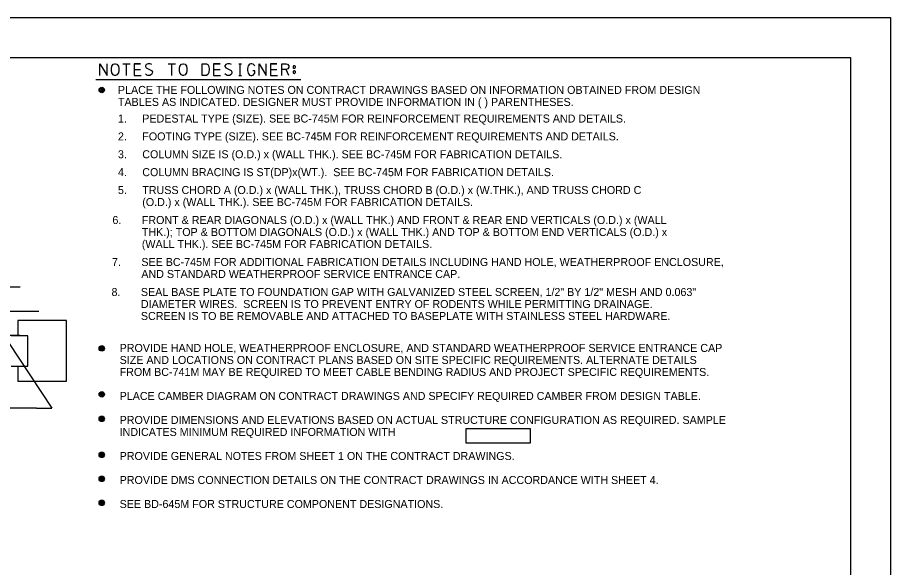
# Model space of a CAD drawing. Extents: x 3831399 to 3833095, y 499014 to 500202.
# Drawn here: x 3832754.1 to 3833081.2, y 499995.8 to 500202 of the extents above; entities that cross this region are included whole.
import ezdxf

# ---------------------------------------------------------------- set-up
doc = ezdxf.new("R2010")
doc.units = 0
for name, color, linetype in [('0-conc', 7, 'Continuous'), ('0-DEVICE ATTACH', 7, 'Continuous'), ('2', 7, 'Continuous'), ('CenterLine', 7, 'Continuous'), ('DIM TXT', 7, 'Continuous'), ('PLT-BNDY', 7, 'Continuous')]:
    doc.layers.add(name, color=color, linetype=linetype)

msp = doc.modelspace()

# ---------------------------------------------------------------- linework, layer by layer
at = {"layer": '0-conc'}
for p, q in [((3832772.44, 500088.38), (3832754.26, 500088.38)), ((3832754.26, 500088.38), (3832754.26, 500082.68)), ((3832772.44, 500065.64), (3832772.44, 500088.38)), ((3832754.26, 500071.31), (3832754.26, 500065.64)), ((3832754.26, 500065.64), (3832772.44, 500065.64))]:
    msp.add_line(p, q, dxfattribs=at)
at = {"layer": '0-DEVICE ATTACH'}
for p, q in [((3832757.96, 500082.68), (3832751.71, 500082.68)), ((3832757.96, 500078.03), (3832757.96, 500082.68)), ((3832757.96, 500071.31), (3832757.96, 500078.03)), ((3832751.71, 500071.31), (3832757.96, 500071.31))]:
    msp.add_line(p, q, dxfattribs=at)
at = {"layer": '2'}
for p, q in [((3832280.16, 500187.03), (3833066.16, 500187.03)), ((3833066.16, 500187.03), (3833066.16, 499623.03))]:
    msp.add_line(p, q, dxfattribs=at)
at = {"layer": 'CenterLine'}
for p, q in [((3832324.19, 500101.07), (3832755.03, 500101.07)), ((3832324.19, 500091.98), (3832755.03, 500091.98)), ((3832706.69, 500091.98), (3832762.11, 500091.98)), ((3832324.19, 500082.88), (3832755.03, 500082.88))]:
    msp.add_line(p, q, dxfattribs=at)
at = {"layer": 'DIM TXT'}
for p, q in [((3832793.5, 500184.7), (3832796.31, 500184.7)), ((3832794.91, 500180.31), (3832794.91, 500184.7)), ((3832794.91, 500180.31), (3832794.91, 500184.7)), ((3832797.75, 500184.7), (3832800.2, 500184.7)), ((3832810.52, 500184.7), (3832813.33, 500184.7)), ((3832811.93, 500180.31), (3832811.93, 500184.7)), ((3832811.93, 500180.31), (3832811.93, 500184.7)), ((3832827.54, 500184.7), (3832829.99, 500184.7)), ((3832836.99, 500184.7), (3832838, 500184.7)), ((3832837.49, 500180.31), (3832837.49, 500184.7)), ((3832848.82, 500184.7), (3832851.27, 500184.7)), ((3832797.75, 500182.52), (3832800.2, 500182.52)), ((3832797.75, 500182.52), (3832800.2, 500182.52)), ((3832827.54, 500182.52), (3832829.99, 500182.52)), ((3832827.54, 500182.52), (3832829.99, 500182.52)), ((3832848.82, 500182.52), (3832851.27, 500182.52)), ((3832848.82, 500182.52), (3832851.27, 500182.52)), ((3832855.72, 500180.31), (3832854.75, 500182.56)), ((3832783.48, 500178.83), (3832860.19, 500178.83)), ((3832836.99, 500180.31), (3832838, 500180.31)), ((3832743.36, 500091.18), (3832767, 500055.57)), ((3832761.18, 500055.57), (3832745.2, 500055.57)), ((3832761.18, 500055.57), (3832767, 500055.57)), ((3832946.33, 500047.84), (3832922.08, 500047.84)), ((3832922.08, 500047.84), (3832922.08, 500042.59)), ((3832946.33, 500042.59), (3832946.33, 500047.84)), ((3832922.08, 500042.59), (3832946.33, 500042.59))]:
    msp.add_line(p, q, dxfattribs=at)
for points in [[(3832784.99, 500180.31), (3832784.99, 500184.7), (3832787.63, 500180.31), (3832787.63, 500184.7)], [(3832790.45, 500184.7), (3832790.78, 500184.7), (3832791.35, 500184.46), (3832791.89, 500183.73), (3832792.02, 500182.87), (3832792.02, 500182.08), (3832791.89, 500181.21), (3832791.32, 500180.49), (3832790.78, 500180.31), (3832790.45, 500180.31), (3832789.95, 500180.49), (3832789.38, 500181.21), (3832789.24, 500182.08), (3832789.24, 500182.87), (3832789.38, 500183.77), (3832789.95, 500184.49), (3832790.45, 500184.7)], [(3832800.2, 500184.7), (3832797.75, 500184.7), (3832797.75, 500180.31), (3832800.37, 500180.31)], [(3832804.46, 500184.39), (3832803.79, 500184.7), (3832803.01, 500184.7), (3832802.31, 500184.39), (3832802.01, 500183.84), (3832802.01, 500183.63), (3832802.34, 500183.11), (3832804.29, 500182.08), (3832804.62, 500181.59), (3832804.59, 500181.18), (3832804.29, 500180.63), (3832803.72, 500180.31), (3832802.91, 500180.31), (3832802.55, 500180.45), (3832802.01, 500180.83)], [(3832815.98, 500184.7), (3832816.32, 500184.7), (3832816.89, 500184.46), (3832817.42, 500183.73), (3832817.56, 500182.87), (3832817.56, 500182.08), (3832817.42, 500181.21), (3832816.85, 500180.49), (3832816.32, 500180.31), (3832815.98, 500180.31), (3832815.48, 500180.49), (3832814.91, 500181.21), (3832814.78, 500182.08), (3832814.78, 500182.87), (3832814.91, 500183.77), (3832815.48, 500184.49), (3832815.98, 500184.7)], [(3832823.29, 500184.7), (3832824.83, 500184.7), (3832825.4, 500184.39), (3832825.77, 500183.63), (3832825.93, 500182.63), (3832825.73, 500181.39), (3832825.36, 500180.63), (3832824.83, 500180.31), (3832823.29, 500180.31), (3832823.29, 500184.7)], [(3832829.99, 500184.7), (3832827.54, 500184.7), (3832827.54, 500180.31), (3832830.16, 500180.31)], [(3832834.24, 500184.39), (3832833.57, 500184.7), (3832832.8, 500184.7), (3832832.1, 500184.39), (3832831.8, 500183.84), (3832831.8, 500183.63), (3832832.13, 500183.11), (3832834.08, 500182.08), (3832834.41, 500181.59), (3832834.38, 500181.18), (3832834.08, 500180.63), (3832833.51, 500180.31), (3832832.7, 500180.31), (3832832.33, 500180.45), (3832831.8, 500180.83)], [(3832842.96, 500183.84), (3832842.39, 500184.56), (3832841.85, 500184.7), (3832841.45, 500184.7), (3832841.01, 500184.56), (3832840.44, 500183.84), (3832840.31, 500182.91), (3832840.31, 500182.18), (3832840.48, 500181.14), (3832840.98, 500180.45), (3832841.48, 500180.31), (3832841.85, 500180.31), (3832842.39, 500180.45), (3832842.96, 500181.18), (3832842.96, 500182.04), (3832842.22, 500182.04)], [(3832844.56, 500180.31), (3832844.56, 500184.7), (3832847.21, 500180.31), (3832847.21, 500184.7)], [(3832851.27, 500184.7), (3832848.82, 500184.7), (3832848.82, 500180.31), (3832851.43, 500180.31)], [(3832853.07, 500180.31), (3832853.07, 500184.7), (3832854.78, 500184.7), (3832855.29, 500184.53), (3832855.72, 500183.84), (3832855.72, 500183.42), (3832855.32, 500182.73), (3832854.78, 500182.56), (3832853.07, 500182.56)], [(3832858.24, 500183.35), (3832858.24, 500183.49), (3832858.2, 500183.63), (3832858.13, 500183.73), (3832858, 500183.84), (3832857.87, 500183.91), (3832857.67, 500183.91), (3832857.53, 500183.84), (3832857.4, 500183.7), (3832857.33, 500183.56), (3832857.33, 500183.35), (3832857.4, 500183.18), (3832857.53, 500183.04), (3832857.7, 500182.97), (3832857.87, 500182.97), (3832858.03, 500183.04), (3832858.17, 500183.18), (3832858.24, 500183.35)], [(3832858.24, 500181.45), (3832858.24, 500181.59), (3832858.2, 500181.73), (3832858.13, 500181.83), (3832858, 500181.94), (3832857.87, 500182.01), (3832857.67, 500182.01), (3832857.53, 500181.94), (3832857.4, 500181.8), (3832857.33, 500181.66), (3832857.33, 500181.45), (3832857.4, 500181.28), (3832857.53, 500181.14), (3832857.7, 500181.07), (3832857.87, 500181.07), (3832858.03, 500181.14), (3832858.17, 500181.28), (3832858.24, 500181.45)]]:
    msp.add_lwpolyline(points, dxfattribs=at)
for centre, major_axis in [((3832785.64, 500174.83), (0, 1.04)), ((3832785.64, 500174.83), (0, 0.783)), ((3832785.64, 500174.83), (0, 0.522)), ((3832785.64, 500174.83), (0, 0.261)), ((3832785.64, 500174.83), (0, 0.00000209)), ((3832785.64, 500077.95), (0, 1.04)), ((3832785.64, 500077.95), (0, 0.783)), ((3832785.64, 500077.95), (0, 0.522)), ((3832785.64, 500077.95), (0, 0.261)), ((3832785.64, 500077.95), (0, 0.00000209)), ((3832785.64, 500060.75), (0, 1.04)), ((3832785.64, 500060.75), (0, 0.783)), ((3832785.64, 500060.75), (0, 0.522)), ((3832785.64, 500060.75), (0, 0.261)), ((3832785.64, 500060.75), (0, 0.00000209)), ((3832785.64, 500051.55), (0, 1.04)), ((3832785.64, 500051.55), (0, 0.783)), ((3832785.64, 500051.55), (0, 0.522)), ((3832785.64, 500051.55), (0, 0.261)), ((3832785.64, 500051.55), (0, 0.00000209)), ((3832785.64, 500038.05), (0, 1.04)), ((3832785.64, 500038.05), (0, 0.783)), ((3832785.64, 500038.05), (0, 0.522)), ((3832785.64, 500038.05), (0, 0.261)), ((3832785.64, 500038.05), (0, 0.00000209)), ((3832785.64, 500029.05), (0, 1.04)), ((3832785.64, 500029.05), (0, 0.783)), ((3832785.64, 500029.05), (0, 0.522)), ((3832785.64, 500029.05), (0, 0.261)), ((3832785.64, 500029.05), (0, 0.00000209)), ((3832785.64, 500020.05), (0, 1.04)), ((3832785.64, 500020.05), (0, 0.783)), ((3832785.64, 500020.05), (0, 0.522)), ((3832785.64, 500020.05), (0, 0.261)), ((3832785.64, 500020.05), (0, 0.00000209))]:
    msp.add_ellipse(centre, major_axis=major_axis, ratio=0.97, dxfattribs=at)
at = {"layer": 'PLT-BNDY'}
msp.add_lwpolyline([(3832240.16, 500202.03), (3833081.16, 500202.03), (3833081.16, 499608.03), (3832240.16, 499608.03)], close=True, dxfattribs=at)

# ---------------------------------------------------------------- texts
at = {"layer": 'DIM TXT'}
for s, height, p in [('PLACE THE FOLLOWING NOTES ON CONTRACT DRAWINGS BASED ON INFORMATION OBTAINED FROM DESIGN ', 2.9999, (3832791.71, 500173.36)), ('TABLES AS INDICATED. DESIGNER MUST PROVIDE INFORMATION IN ( ) PARENTHESES. ', 2.9999, (3832791.71, 500168.86)), ('1.', 3, (3832791.71, 500162.64)), ('PEDESTAL TYPE (SIZE). SEE BC-745M FOR REINFORCEMENT REQUIREMENTS AND DETAILS.', 2.9999, (3832800.83, 500162.64)), ('2.', 3, (3832791.71, 500155.94)), ('FOOTING TYPE (SIZE). SEE BC-745M FOR REINFORCEMENT REQUIREMENTS AND DETAILS.', 2.9999, (3832800.83, 500155.94)), ('3.', 3, (3832791.71, 500149.24)), ('COLUMN SIZE IS (O.D.) x (WALL THK.). SEE BC-745M FOR FABRICATION DETAILS.', 2.9999, (3832800.83, 500149.24)), ('4.', 3, (3832791.71, 500142.53)), ('COLUMN BRACING IS ST(DP)x(WT.).  SEE BC-745M FOR FABRICATION DETAILS.', 2.9999, (3832800.83, 500142.53)), ('5.', 3, (3832791.71, 500135.83)), ('TRUSS CHORD A (O.D.) x (WALL THK.), TRUSS CHORD B (O.D.) x (W.THK.), AND TRUSS CHORD C ', 2.9999, (3832800.83, 500135.83)), ('(O.D.) x (WALL THK.). SEE BC-745M FOR FABRICATION DETAILS.', 2.9999, (3832800.83, 500131.33)), (' 6.', 3, (3832788.53, 500124.59)), ('FRONT & REAR DIAGONALS (O.D.) x (WALL THK.) AND FRONT & REAR END VERTICALS (O.D.) x (WALL ', 2.9999, (3832800.66, 500124.59)), ('THK.); TOP & BOTTOM DIAGONALS (O.D.) x (WALL THK.) AND TOP & BOTTOM END VERTICALS (O.D.) x ', 2.9999, (3832800.66, 500120.09)), ('(WALL THK.). SEE BC-745M FOR FABRICATION DETAILS.', 2.9999, (3832800.66, 500115.59)), (' 7.', 3, (3832788.36, 500108.85)), ('SEE BC-745M FOR ADDITIONAL FABRICATION DETAILS INCLUDING HAND HOLE, WEATHERPROOF ENCLOSURE, ', 2.9999, (3832800.48, 500108.85)), ('AND STANDARD WEATHERPROOF SERVICE ENTRANCE CAP.', 2.9999, (3832800.48, 500104.35)), (' 8.', 3, (3832788.19, 500097.6)), ('SEAL BASE PLATE TO FOUNDATION GAP WITH GALVANIZED STEEL SCREEN, 1/2" BY 1/2" MESH AND 0.063" ', 2.9999, (3832800.31, 500097.6)), ('DIAMETER WIRES.  SCREEN IS TO PREVENT ENTRY OF RODENTS WHILE PERMITTING DRAINAGE.', 2.9999, (3832800.31, 500093.1)), ('SCREEN IS TO BE REMOVABLE AND ATTACHED TO BASEPLATE WITH STAINLESS STEEL HARDWARE.', 2.9999, (3832800.31, 500088.61)), ('PROVIDE HAND HOLE, WEATHERPROOF ENCLOSURE, AND STANDARD WEATHERPROOF SERVICE ENTRANCE CAP ', 2.9999, (3832792.35, 500076.63)), ('SIZE AND LOCATIONS ON CONTRACT PLANS BASED ON SITE SPECIFIC REQUIREMENTS. ALTERNATE DETAILS ', 2.9999, (3832792.35, 500072.13)), ('FROM BC-741M MAY BE REQUIRED TO MEET CABLE BENDING RADIUS AND PROJECT SPECIFIC REQUIREMENTS.', 2.9999, (3832792.35, 500067.63)), ('PLACE CAMBER DIAGRAM ON CONTRACT DRAWINGS AND SPECIFY REQUIRED CAMBER FROM DESIGN TABLE.', 2.9999, (3832792.35, 500058.63)), ('PROVIDE DIMENSIONS AND ELEVATIONS BASED ON ACTUAL STRUCTURE CONFIGURATION AS REQUIRED. SAMPLE ', 2.9999, (3832792.35, 500049.63)), ('INDICATES MINIMUM REQUIRED INFORMATION WITH ', 2.9999, (3832792.35, 500045.13)), ('PROVIDE GENERAL NOTES FROM SHEET 1 ON THE CONTRACT DRAWINGS.', 2.9999, (3832792.35, 500036.13)), ('PROVIDE DMS CONNECTION DETAILS ON THE CONTRACT DRAWINGS IN ACCORDANCE WITH SHEET 4.', 2.9999, (3832792.35, 500027.13)), ('SEE BD-645M FOR STRUCTURE COMPONENT DESIGNATIONS.', 2.9999, (3832792.35, 500018.13))]:
    msp.add_text(s, height=height, dxfattribs=at).set_placement(p)

doc.saveas('drawing.dxf')
